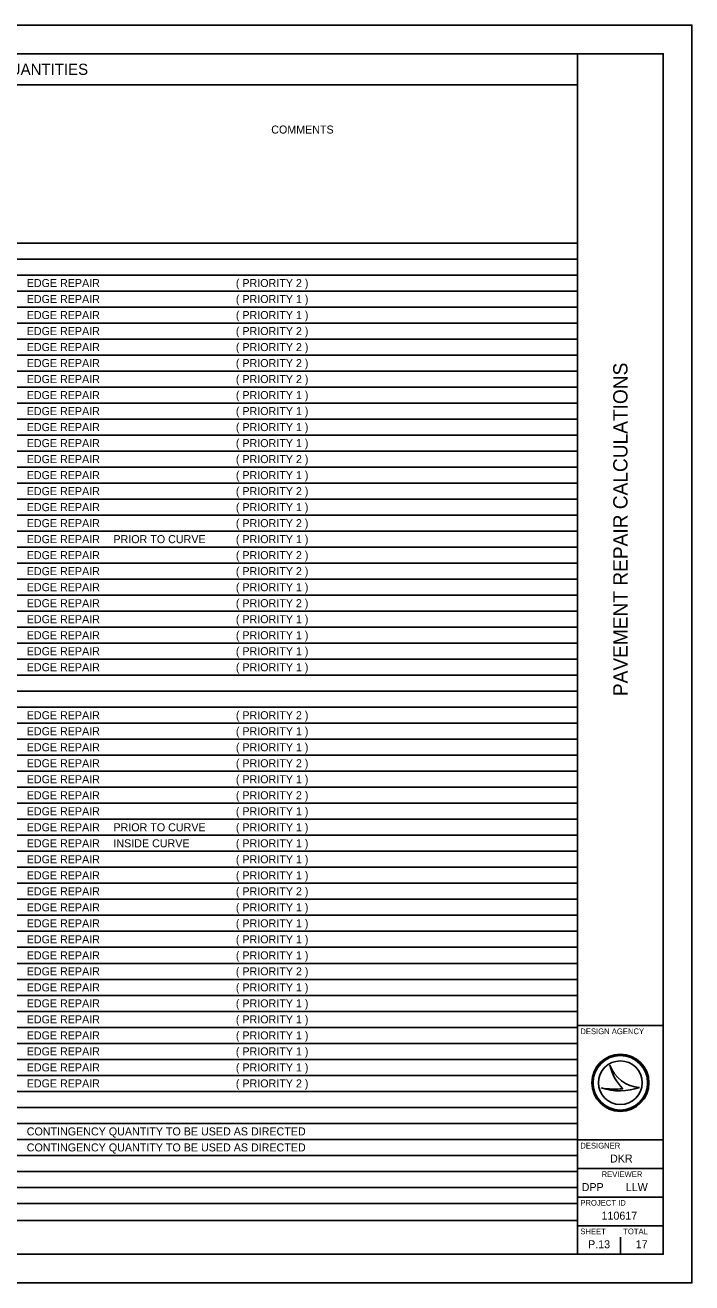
# Model space of a CAD drawing. Extents: x 0 to 34, y 0 to 22.
# Drawn here: x 22.34 to 34, y 0 to 22 of the extents above; entities that cross this region are included whole.
import ezdxf

# ---------------------------------------------------------------- set-up
doc = ezdxf.new("R2010")
doc.units = 0
for name, color, linetype in [('SH_Border', 7, 'Continuous'), ('SH_Cut_Line', 7, 'Continuous'), ('SH_Data', 7, 'Continuous')]:
    doc.layers.add(name, color=color, linetype=linetype)

msp = doc.modelspace()

# ---------------------------------------------------------------- linework, layer by layer
at = {"layer": 'SH_Border'}
for p, q in [((32, 0.5), (32, 21.5)), ((32, 4.5), (33.5, 4.5)), ((32, 2.5), (33.5, 2.5)), ((32, 2), (33.5, 2)), ((32, 1.5), (33.5, 1.5)), ((32, 1), (33.5, 1))]:
    msp.add_line(p, q, dxfattribs=at)
msp.add_lwpolyline([(1.5, 21.5), (33.5, 21.5), (33.5, 0.5), (1.5, 0.5)], close=True, dxfattribs=at)
at = {"layer": 'SH_Cut_Line'}
msp.add_lwpolyline([(0, 0), (34, 0), (34, 22), (0, 22)], close=True, dxfattribs=at)
at = {"layer": 'SH_Data'}
for p, q in [((1.5, 20.956), (32.004, 20.956)), ((1.5, 18.189), (32.004, 18.189)), ((1.5, 17.909), (32.004, 17.909)), ((1.5, 17.629), (32.004, 17.629)), ((1.5, 17.349), (32.004, 17.349)), ((1.5, 17.069), (32.004, 17.069)), ((1.5, 16.789), (32.004, 16.789)), ((1.5, 16.509), (32.004, 16.509)), ((1.5, 16.229), (32.004, 16.229)), ((1.5, 15.949), (32.004, 15.949)), ((1.5, 15.669), (32.004, 15.669)), ((1.5, 15.389), (32.004, 15.389)), ((1.5, 15.109), (32.004, 15.109)), ((1.5, 14.829), (32.004, 14.829)), ((1.5, 14.549), (32.004, 14.549)), ((1.5, 14.269), (32.004, 14.269)), ((1.5, 13.989), (32.004, 13.989)), ((1.5, 13.709), (32.004, 13.709)), ((1.5, 13.429), (32.004, 13.429)), ((1.5, 13.149), (32.004, 13.149)), ((1.5, 12.869), (32.004, 12.869)), ((1.5, 12.589), (32.004, 12.589)), ((1.5, 12.309), (32.004, 12.309)), ((1.5, 12.029), (32.004, 12.029)), ((1.5, 11.749), (32.004, 11.749)), ((1.5, 11.469), (32.004, 11.469)), ((1.5, 11.189), (32.004, 11.189)), ((1.5, 10.909), (32.004, 10.909)), ((1.5, 10.629), (32.004, 10.629)), ((1.5, 10.349), (32.004, 10.349)), ((1.5, 10.069), (32.004, 10.069)), ((1.5, 9.789), (32.004, 9.789)), ((1.5, 9.509), (32.004, 9.509)), ((1.5, 9.229), (32.004, 9.229)), ((1.5, 8.949), (32.004, 8.949)), ((1.5, 8.669), (32.004, 8.669)), ((1.5, 8.389), (32.004, 8.389)), ((1.5, 8.109), (32.004, 8.109)), ((1.5, 7.829), (32.004, 7.829)), ((1.5, 7.549), (32.004, 7.549)), ((1.5, 7.269), (32.004, 7.269)), ((1.5, 6.989), (32.004, 6.989)), ((1.5, 6.709), (32.004, 6.709)), ((1.5, 6.429), (32.004, 6.429)), ((1.5, 6.149), (32.004, 6.149)), ((1.5, 5.869), (32.004, 5.869)), ((1.5, 5.589), (32.004, 5.589)), ((1.5, 5.309), (32.004, 5.309)), ((1.5, 5.029), (32.004, 5.029)), ((1.5, 4.749), (32.004, 4.749)), ((1.5, 4.469), (32.004, 4.469)), ((1.5, 4.189), (32.004, 4.189)), ((1.5, 3.909), (32.004, 3.909)), ((32.567, 3.81), (32.567, 3.81)), ((1.5, 3.629), (32.004, 3.629)), ((1.5, 3.349), (32.004, 3.349)), ((32.417, 3.41), (32.417, 3.41)), ((32.75, 3.5), (32.75, 3.5)), ((33.087, 3.419), (33.087, 3.419)), ((1.5, 3.069), (32.004, 3.069)), ((1.5, 2.789), (32.004, 2.789)), ((1.5, 2.509), (32.004, 2.509)), ((1.5, 2.229), (32.004, 2.229)), ((1.5, 1.949), (32.004, 1.949)), ((1.5, 1.669), (32.004, 1.669)), ((1.5, 1.389), (32.004, 1.389)), ((1.5, 1.093), (32.004, 1.093)), ((32.375, 0.675), (32.375, 0.675)), ((32.75, 0.5), (32.75, 0.8))]:
    msp.add_line(p, q, dxfattribs=at)
for radius in [0.5, 0.477, 0.477, 0.382]:
    msp.add_circle((32.75, 3.5), radius, dxfattribs=at)
for centre, radius, start, end in [((33.116, 3.998), 0.58, 198.9257, 198.9319), ((33.347, 3.97), 0.796, 191.6379, 191.6421), ((33.116, 3.998), 0.58, 198.9319, 267.1657), ((33.347, 3.97), 0.796, 191.6421, 226.0947), ((32.739, 4.37), 1.013, 251.4576, 290.0832), ((32.648, 4.654), 1.266, 259.4964, 259.4995), ((32.739, 4.37), 1.013, 251.4527, 251.4576), ((32.648, 4.654), 1.266, 259.4995, 276.6672)]:
    msp.add_arc(centre, radius, start, end, dxfattribs=at)

# ---------------------------------------------------------------- texts
for s, height, p in [('QUANTITIES', 0.196, (21.868, 21.13)), ('COMMENTS', 0.14, (26.644, 20.104)), ('EDGE REPAIR', 0.14, (22.368, 17.419)), ('( PRIORITY 2 )', 0.14, (26.025, 17.419)), ('EDGE REPAIR', 0.14, (22.368, 17.139)), ('( PRIORITY 1 )', 0.14, (26.025, 17.139)), ('EDGE REPAIR', 0.14, (22.368, 16.859)), ('( PRIORITY 1 )', 0.14, (26.025, 16.859)), ('EDGE REPAIR', 0.14, (22.368, 16.579)), ('( PRIORITY 2 )', 0.14, (26.025, 16.579)), ('EDGE REPAIR', 0.14, (22.368, 16.299)), ('( PRIORITY 2 )', 0.14, (26.025, 16.299)), ('EDGE REPAIR', 0.14, (22.368, 16.019)), ('( PRIORITY 2 )', 0.14, (26.025, 16.019)), ('EDGE REPAIR', 0.14, (22.368, 15.739)), ('( PRIORITY 2 )', 0.14, (26.025, 15.739)), ('EDGE REPAIR', 0.14, (22.368, 15.459)), ('( PRIORITY 1 )', 0.14, (26.025, 15.459)), ('EDGE REPAIR', 0.14, (22.368, 15.179)), ('( PRIORITY 1 )', 0.14, (26.025, 15.179)), ('EDGE REPAIR', 0.14, (22.368, 14.899)), ('( PRIORITY 1 )', 0.14, (26.025, 14.899)), ('EDGE REPAIR', 0.14, (22.368, 14.619)), ('( PRIORITY 1 )', 0.14, (26.025, 14.619)), ('EDGE REPAIR', 0.14, (22.368, 14.339)), ('( PRIORITY 2 )', 0.14, (26.025, 14.339)), ('EDGE REPAIR', 0.14, (22.368, 14.059)), ('( PRIORITY 1 )', 0.14, (26.025, 14.059)), ('EDGE REPAIR', 0.14, (22.368, 13.779)), ('( PRIORITY 2 )', 0.14, (26.025, 13.779)), ('EDGE REPAIR', 0.14, (22.368, 13.499)), ('( PRIORITY 1 )', 0.14, (26.025, 13.499)), ('EDGE REPAIR', 0.14, (22.368, 13.219)), ('( PRIORITY 2 )', 0.14, (26.025, 13.219)), ('EDGE REPAIR', 0.14, (22.368, 12.939)), ('PRIOR TO CURVE', 0.14, (23.884, 12.939)), ('( PRIORITY 1 )', 0.14, (26.025, 12.939)), ('EDGE REPAIR', 0.14, (22.368, 12.659)), ('( PRIORITY 2 )', 0.14, (26.025, 12.659)), ('EDGE REPAIR', 0.14, (22.368, 12.379)), ('( PRIORITY 2 )', 0.14, (26.025, 12.379)), ('EDGE REPAIR', 0.14, (22.368, 12.099)), ('( PRIORITY 1 )', 0.14, (26.025, 12.099)), ('EDGE REPAIR', 0.14, (22.368, 11.819)), ('( PRIORITY 2 )', 0.14, (26.025, 11.819)), ('EDGE REPAIR', 0.14, (22.368, 11.539)), ('( PRIORITY 1 )', 0.14, (26.025, 11.539)), ('EDGE REPAIR', 0.14, (22.368, 11.259)), ('( PRIORITY 1 )', 0.14, (26.025, 11.259)), ('EDGE REPAIR', 0.14, (22.368, 10.979)), ('( PRIORITY 1 )', 0.14, (26.025, 10.979)), ('EDGE REPAIR', 0.14, (22.368, 10.699)), ('( PRIORITY 1 )', 0.14, (26.025, 10.699)), ('EDGE REPAIR', 0.14, (22.368, 9.859)), ('( PRIORITY 2 )', 0.14, (26.025, 9.859)), ('EDGE REPAIR', 0.14, (22.368, 9.579)), ('( PRIORITY 1 )', 0.14, (26.025, 9.579)), ('EDGE REPAIR', 0.14, (22.368, 9.299)), ('( PRIORITY 1 )', 0.14, (26.025, 9.299)), ('EDGE REPAIR', 0.14, (22.368, 9.019)), ('( PRIORITY 2 )', 0.14, (26.025, 9.019)), ('EDGE REPAIR', 0.14, (22.368, 8.739)), ('( PRIORITY 1 )', 0.14, (26.025, 8.739)), ('EDGE REPAIR', 0.14, (22.368, 8.459)), ('( PRIORITY 2 )', 0.14, (26.025, 8.459)), ('EDGE REPAIR', 0.14, (22.368, 8.179)), ('( PRIORITY 1 )', 0.14, (26.025, 8.179)), ('EDGE REPAIR', 0.14, (22.368, 7.899)), ('PRIOR TO CURVE', 0.14, (23.884, 7.899)), ('( PRIORITY 1 )', 0.14, (26.025, 7.899)), ('EDGE REPAIR', 0.14, (22.368, 7.619)), ('INSIDE CURVE', 0.14, (23.884, 7.619)), ('( PRIORITY 1 )', 0.14, (26.025, 7.619)), ('EDGE REPAIR', 0.14, (22.368, 7.339)), ('( PRIORITY 1 )', 0.14, (26.025, 7.339)), ('EDGE REPAIR', 0.14, (22.368, 7.059)), ('( PRIORITY 1 )', 0.14, (26.025, 7.059)), ('EDGE REPAIR', 0.14, (22.368, 6.779)), ('( PRIORITY 2 )', 0.14, (26.025, 6.779)), ('EDGE REPAIR', 0.14, (22.368, 6.499)), ('( PRIORITY 1 )', 0.14, (26.025, 6.499)), ('EDGE REPAIR', 0.14, (22.368, 6.219)), ('( PRIORITY 1 )', 0.14, (26.025, 6.219)), ('EDGE REPAIR', 0.14, (22.368, 5.939)), ('( PRIORITY 1 )', 0.14, (26.025, 5.939)), ('EDGE REPAIR', 0.14, (22.368, 5.659)), ('( PRIORITY 1 )', 0.14, (26.025, 5.659)), ('EDGE REPAIR', 0.14, (22.368, 5.379)), ('( PRIORITY 2 )', 0.14, (26.025, 5.379)), ('EDGE REPAIR', 0.14, (22.368, 5.099)), ('( PRIORITY 1 )', 0.14, (26.025, 5.099)), ('EDGE REPAIR', 0.14, (22.368, 4.819)), ('( PRIORITY 1 )', 0.14, (26.025, 4.819)), ('EDGE REPAIR', 0.14, (22.368, 4.539)), ('( PRIORITY 1 )', 0.14, (26.025, 4.539)), ('EDGE REPAIR', 0.14, (22.368, 4.259)), ('( PRIORITY 1 )', 0.14, (26.025, 4.259)), ('DESIGN AGENCY', 0.1, (32.05, 4.35)), ('EDGE REPAIR', 0.14, (22.368, 3.979)), ('( PRIORITY 1 )', 0.14, (26.025, 3.979)), ('EDGE REPAIR', 0.14, (22.368, 3.699)), ('( PRIORITY 1 )', 0.14, (26.025, 3.699)), ('EDGE REPAIR', 0.14, (22.368, 3.419)), ('( PRIORITY 2 )', 0.14, (26.025, 3.419)), ('CONTINGENCY QUANTITY TO BE USED AS DIRECTED', 0.14, (22.368, 2.579)), ('CONTINGENCY QUANTITY TO BE USED AS DIRECTED', 0.14, (22.368, 2.299)), ('DESIGNER', 0.1, (32.05, 2.35)), ('DKR', 0.14, (32.569, 2.105)), ('REVIEWER', 0.1, (32.422, 1.85)), ('DPP', 0.14, (32.073, 1.605)), ('LLW', 0.14, (32.844, 1.605)), ('PROJECT ID', 0.1, (32.05, 1.35)), ('110617', 0.14, (32.42, 1.105)), ('SHEET', 0.1, (32.05, 0.85)), ('TOTAL', 0.1, (32.8, 0.85)), ('P.13', 0.14, (32.185, 0.605)), ('17', 0.14, (33.018, 0.605))]:
    msp.add_text(s, height=height, dxfattribs=at).set_placement(p)
msp.add_text('PAVEMENT REPAIR CALCULATIONS', height=0.25, rotation=90, dxfattribs=at).set_placement((32.875, 10.263))

doc.saveas('drawing.dxf')
